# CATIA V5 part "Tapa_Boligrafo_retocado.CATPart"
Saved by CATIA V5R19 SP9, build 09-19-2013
Part number: Tapa boligrafo
Bounding box of the stored display mesh (mm): x -5 to 15, y -5 to 5, z -56.5 to 0
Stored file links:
  D:\TEMP\Tapa_Boligrafo_retocado.CATPart
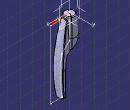
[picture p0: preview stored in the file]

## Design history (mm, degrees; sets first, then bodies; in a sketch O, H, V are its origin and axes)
WSupportSet1: ActiveGrid {wsupport Support Plane1, GridIn {cartgrid SpacingH 100, StepH 10, SpacingV 100, StepV 10, Direction (0, 0, 1)}}
AxisSystem1: origin (0, 0, 0), X (1, 0, 0), Y (0, 1, 0), Z (0, 0, 1)
AxisSystem2: origin (0, 0, 0), X (1, 0, 0), Y (0, 1, 0), Z (0, 0, 1)
Set1
  Plane1: type Offset, RefPlane ZX plane of AxisSystem1, Offset 0
Body1 (main body)
  Body2 "Body.6"
    Sketch1 "Sketch.2" on YZ plane of AxisSystem1, origin (0, 0, 0), H (0, 1, 0), V (0, 0, 1)
      arc A1 centre (0, -10) radius 10 from (0, 0) to (-3.5, -0.6325) ccw
      point P1 (0, -10)
      line L1 (-3.5, -0.6325) -> (-3.5, -1.2)
      line L2 (-3.5, -1.2) -> (-4.043, -1.2)
      axis line L3 (0, 38.1185) -> (0, -65.074)
      point P5 (0, 38.1185)
      line L4 (-5, -15) -> (-5, -30)
      point P7 (-5, -15)
      construction line L5 (-4.043, -1.2) -> (-4.043, 10.5649)
      arc A2 centre (95, -15) radius 100 from (-4.0432, -1.2) to (-5, -15) ccw
      point P11 (-5, -15)
      point P12 (-4.0432, -1.2)
      line L6 (-5, -30) -> (0, -30)
      point P13 (0, -30)
      radius A1 = 10
      distance L2 H = 1.2
      distance L1 V = 3.5
      length L4 = 15
      distance L4 L3 = 5
      distance L5 L3 = 4.043
      radius A2 = 100
      distance L6 H = 30
      coincidence: P1 V, P5 V, P11 P7, L2 P12, L3 P13
      vertical: L1 V, L3 V, L4 V, L5 V
      horizontal: L2 H, L6 H
      tangency: A2 L4
    Shaft1: profile Sketch1, axis Sketch1.L3, angle 360
    Fillet1 "EdgeFillet.2": radius 1, on edge [face of Shaft1 from Sketch1.L1 | face of Shaft1 from Sketch1.L2]
    Sketch2 on ZX plane of AxisSystem1, origin (0, 0, 0), H (0, 0, 1), V (1, 0, 0)
      construction line L1 (-20, 11.6442) -> (-20, -10.3533)
      axis line L2 (-36.5325, 0) -> (9.6797, 0)
      point P3 (-36.5325, 0)
      line L3 (-31.475, 11.475) -> (-11.17, -8.83)
      point P7 (-20, 0)
      distance V L1 = 20
      angle L3 L2 = 135
      vertical: L1 V
      coincidence: P3 H, L2 P7, L1 P7, L3 P7
      horizontal: L2 H
    Pocket1 "Pocket.1": profile Sketch2, direction (0, 1, 0), length 8, mirrored extent
  Assemble1: tool Body2
  Body3
    Sketch3 on YZ plane of AxisSystem1, origin (0, 0, 0), H (0, 1, 0), V (0, 0, 1)
      construction line L1 (0, 0) -> (0, -56.5)
      point P1 (0, -56.5)
      point P2 (0, -51.5)
      arc A1 centre (0, -51.5) radius 5 from (-2.3055, -55.9368) to (0, -56.5) ccw
      construction line L2 (-4, 6.5418) -> (-4, -35)
      arc A2 centre (296, -35) radius 300 from (-4, -35) to (-3.3791, -54.2907) ccw
      point P4 (296, -35)
      construction line L3 (-136.8342, -35) -> (395.1675, -35)
      point P7 (-4, -35)
      point P8 (-4, -35)
      point P9 (0, -83.8262)
      arc A3 centre (296, -35) radius 300 from (0, 13.8262) to (-4, -35) ccw
      point P10 (0, 13.8262)
      point P11 (0, -83.8262)
      point P12 (0, 13.8262)
      point P13 (0, -83.8262)
      point P14 (-2.7174, -7.2888)
      arc A4 centre (-1.3833, -54.1621) radius 2 from (-3.3791, -54.2907) to (-2.3055, -55.9368) ccw
      point P15 (-3.3791, -54.2907)
      point P16 (-2.3055, -55.9368)
      construction line L4 (-2.7174, -7.2888) -> (-13.7985, -126.7398)
      point P19 (0, 13.8262)
      point P20 (2.7174, -7.2888)
      point P21 (4, -35)
      point P22 (2.7174, -7.2888)
      arc A5 centre (-296, -35) radius 300 from (0, 13.8262) to (4, -35) cw
      point P24 (3.3791, -54.2907)
      point P25 (4, -35)
      arc A6 centre (-296, -35) radius 300 from (4, -35) to (3.3791, -54.2907) cw
      point P27 (2.3055, -55.9368)
      point P28 (3.3791, -54.2907)
      arc A7 centre (1.3833, -54.1621) radius 2 from (3.3791, -54.2907) to (2.3055, -55.9368) cw
      point P30 (0, -56.5)
      point P31 (2.3055, -55.9368)
      arc A8 centre (0, -51.5) radius 5 from (2.3055, -55.9368) to (0, -56.5) cw
      length L1 = 56.5
      radius A1 = 5
      distance L2 V = 4
      radius A2 = 300
      distance L3 H = 35
      distance P2 H = 51.5
      radius A4 = 2
      vertical: L1 V, L2 V
      horizontal: L3 H
      coincidence: P4 L3, L2 P7, L3 P8, L1 P9, A3 P10, L1 P10, A3 P11, L1 P11, A3 P12, A3 P13, P1 P30, P10 P19, P20 P22, P21 P25, P24 P28, P27 P31, P14 A3, P22 A5
      tangency: L2 A2, A3 L2, A4 A2, A4 A1, L4 A3
      symmetry: P10 P19 L1, P14 P20 L1, P7 P21 L1, P14 P22 L1, A3 A5 L1, P15 P24 L1, P7 P25 L1, A2 A6 L1, P16 P27 L1, P15 P28 L1, A4 A7 L1, P1 P30 L1, P16 P31 L1, A1 A8 L1
    Sketch4 on ZX plane of AxisSystem1, origin (0, 0, 0), H (0, 0, 1), V (1, 0, 0)
      reference projected line E1 (-15, -5) -> (-25, 5) from edge [face of Shaft1 from Sketch1.L4 | face of Pocket1 from Sketch2.L3]
      axis line L1 (-65.5487, 0) -> (19.6407, 0)
      point P3 (-65.5487, 0)
      line L2 (-20, 0) -> (-26.1561, 6.1561)
      point P5 (-20, 0)
      line L3 (-20, 0) -> (-2, 0)
      construction line L4 (-2, 11.773) -> (-2, -8.7541)
      line L5 (-2, 0) -> (-2, 15)
      line L6 (-2, 15) -> (-56.5, 15)
      point P10 (-56.5, 15)
      construction line L7 (-67.7575, 6) -> (-44.202, 6)
      line L8 (-56.5, 15) -> (-56.5, 6)
      point P13 (-56.5, 6)
      arc A1 centre (-40.8717, -82.6327) radius 90 from (-26.1561, 6.1561) to (-56.5, 6) ccw
      point P15 (-56.5, 6)
      point P17 (-20, 0)
      construction line L9 (-68.9604, 10) -> (11.5332, 10)
      construction arc A2 centre (-36.7351, -105) radius 115 from (-2, 4.6288) to (-56.5, 8.2888) ccw
      construction line L10 (-56.5, 6) -> (-66.5235, 4.2326)
      construction line L11 (-56.5, 8.289) -> (-66.5042, 6.525)
      point P22 (-56.5, 8.289)
      point P24 (-56.5, 8.2888)
      point P25 (-56.5, 8.2888)
      point P26 (-56.5, 8.2888)
      point P27 (-2, 4.6288)
      reference intersected line E2 through (0, 0) direction (0, 1) from XY plane of AxisSystem1
      length L5 = 15
      distance P10 V = 56.5
      distance L7 L1 = 6
      radius A1 = 90
      distance L9 L1 = 10
      angle L10 L1 = 10
      distance L5 E2 = 2
      radius A2 = 115
      coincidence: P3 H, L2 E1, L2 P5, L1 P5, L7 P13, P13 P15, L1 P17, P5 P17, P22 L8, A2 P24, L8 P24, L8 P25, A2 P25, L8 P26, L4 P27
      horizontal: L1 H, L3 H, L6 H, L7 H, L9 H
      vertical: L4 V, L5 V, L8 V
      tangency: A2 L9, L10 A1, A2 L11
      parallelism: L11 L10
    SolidCombine1: FirstComponentProfile Sketch3, FirstComponentDirection Sketch3, SecondComponentProfile Sketch4, SecondComponentDirection Sketch4
    Sketch5 on ZX plane of AxisSystem1, origin (0, 0, 0), H (0, 0, 1), V (1, 0, 0)
      point P1 (-56.5, 8.2888)
      axis line L1 (14.4438, 0) -> (-69.1932, 0)
      point P2 (14.4438, 0)
      reference projected line E1 through (0, 0) direction (0, 1) from edge [XY plane of AxisSystem1 | ZX plane of AxisSystem1]
      point P6 (-36.7351, -105)
      arc A1 centre (-36.7351, -105) radius 115 from (6.0121, 1.7599) to (-65.5602, 6.3288) ccw
      reference projected line E2 through (0, 0) direction (1, 0) from edge [ZX plane of AxisSystem1 | YZ plane of AxisSystem1]
      reference projected line E3 through (0, 0) direction (0, 1) from edge [XY plane of AxisSystem1 | ZX plane of AxisSystem1]
      distance P1 E1 = 56.5
      radius A1 = 115
      distance P6 E2 = 105
      distance P6 E3 = 36.7351
      coincidence: P2 H
      horizontal: L1 H
    Groove1: profile Sketch5, axis Sketch5.L1, angle 45, second angle 45
    Sketch6 on ZX plane of AxisSystem1, origin (0, 0, 0), H (0, 0, 1), V (1, 0, 0)
      projected arc E1 centre (-40.8717, -82.6327) radius 90 from (-26.1561, 6.1561) to (-56.5, 6) ccw from Sketch4.A1
      projected arc E2 centre (-40.8717, -82.6327) radius 90 from (-28.5826, 6.5244) to (-56.5, 6) ccw from Sketch4.A1
      point P2 (-56.5, 6)
      construction line L1 (-51, 27.5038) -> (-51, -28.4955)
      reference projected line E3 through (0, 0) direction (0, 1) from edge [XY plane of AxisSystem1 | ZX plane of AxisSystem1]
      construction line L2 (-82.414, 4.5) -> (45.1081, 4.5)
      axis line L3 (-93.2125, 0) -> (35.1384, 0)
      point P7 (-93.2125, 0)
      arc A1 centre (-57.6248, -8.9578) radius 15 from (-51, 4.5) to (-56.5, 6) ccw
      point P10 (-56.5, 6)
      point P11 (-51, 4.5)
      point P12 (-51, 4.5)
      arc A2 centre (-35.4099, -43.0073) radius 50 from (-28.5826, 6.5244) to (-51, 4.5) ccw
      point P14 (-51, 4.5)
      point P15 (-28.5826, 6.5244)
      distance L1 E3 = 51
      distance L2 L3 = 4.5
      radius A1 = 15
      radius A2 = 50
      vertical: L1 V
      horizontal: L2 H, L3 H
      coincidence: P7 H, P10 E1, P10 P2, L1 P12, L2 P12, P11 P12, P14 P12, E1 P15
      tangency: A2 E1
    Pad1: profile Sketch6, direction (0, 1, 0), length 0.5, mirrored extent
    Fillet2: radius 2, on edge [face of SolidCombine1 from Sketch4.L5 | face of SolidCombine1 from Sketch3.A5]; edge [face of SolidCombine1 from Sketch3.A3 | face of SolidCombine1 from Sketch4.L5]
    Fillet3: radius 0.5, on edge [face of SolidCombine1 from Sketch3.A2 | face of Groove1 from Sketch5.A1]; edge [face of Groove1 from Sketch5.A1 | face of SolidCombine1 from Sketch3.A5]
    Fillet4: radius 0.5, on edge [face of SolidCombine1 from Sketch4.A1 | end face of Pad1]; edge [start face of Pad1 | face of SolidCombine1 from Sketch4.A1]
  Assemble2: tool Body3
